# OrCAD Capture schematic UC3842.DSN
size A
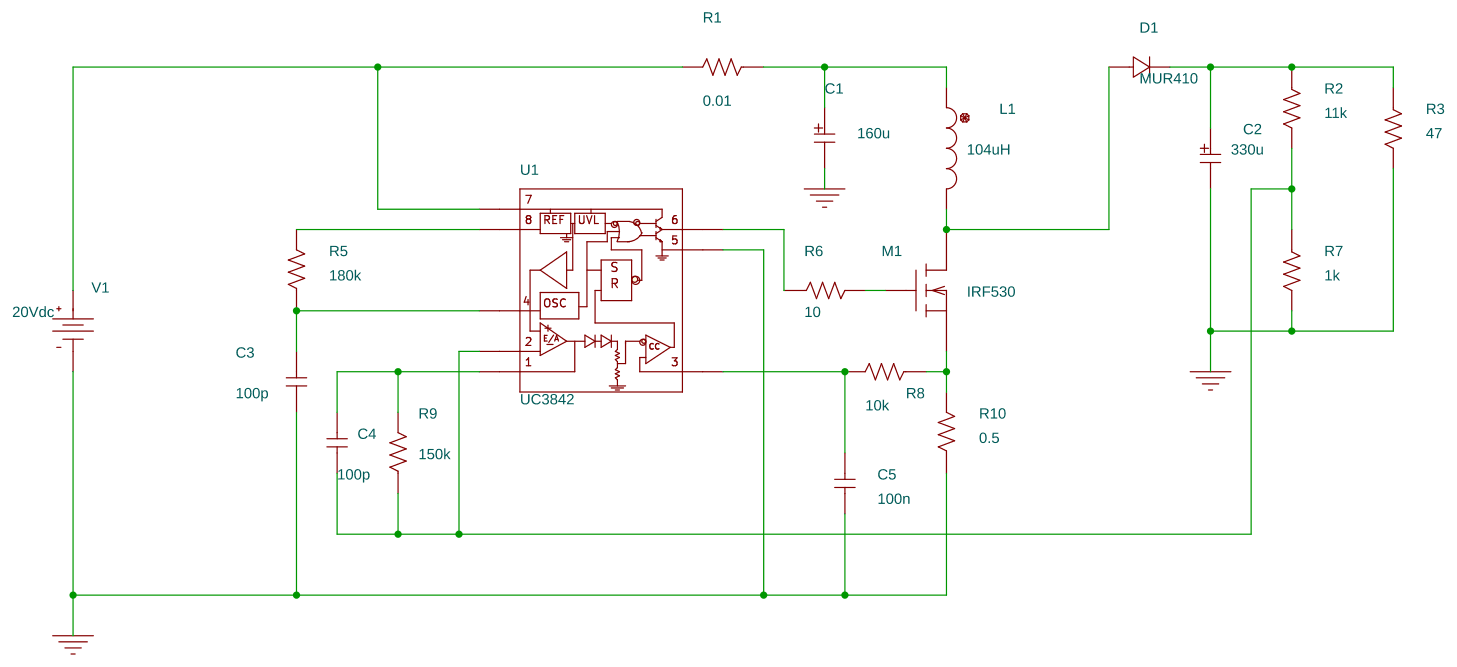
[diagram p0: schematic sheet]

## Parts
C1  160u  [CPAX/.575x.150/.031]
C2  330u  [CPAX/.575x.150/.031]
C3  100p  [RAD/CK05]
C4  100p  [RAD/CK05]
C5  100n  [RAD/CK05]
D1  MUR410  [DO-27]
L1  104uH  [DISC/.350x.175/LS.200x.100/.034]
M1  IRF530  [TO220AB]
R1  0.01  [AX/RC05]
R2  11k  [AX/RC05]
R3  47  [AX/RC05]
R5  180k  [AX/RC05]
R6  10  [AX/RC05]
R7  1k  [AX/RC05]
R8  10k  [AX/RC05]
R9  150k  [AX/RC05]
R10  0.5  [AX/RC05]
U1  UC3842
V1  VDC

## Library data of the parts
C1 C2 = C_elect
C3-C5 = C
D1 = MUR410
L1 = L
M1 = IRF530
R1-R3 R5-R10 = R
U1 = UC3842
V1 = VDC: DC: 20Vdc

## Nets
0: C1.N(-) C2.N(-) C3.1 C5.1 R3.2 R7.2 R10.1 U1.5(GND) V1.1(-)
N14665: R1.2 U1.7(VCC) V1.0(+)
N15071: M1.3(s) R8.1 R10.2
N15085: C5.2 R8.2 U1.3(ISENSE)
N15154: C4.2 R9.2 U1.1(COMP)
N15174: C4.1 R2.2 R7.1 R9.1 U1.2(VFB)
N15514: C2.P(+) D1.1(2) R2.1 R3.1
N17093: C3.2 R5.1 U1.4(RTCT)
N17781: C1.P(+) L1.1 R1.1
N17993: R5.2 U1.8(VREF)
N18231: R6.1 U1.6(DRV)
N21572: D1.2(1) L1.2 M1.2(d)
N22250: M1.1(g) R6.2
